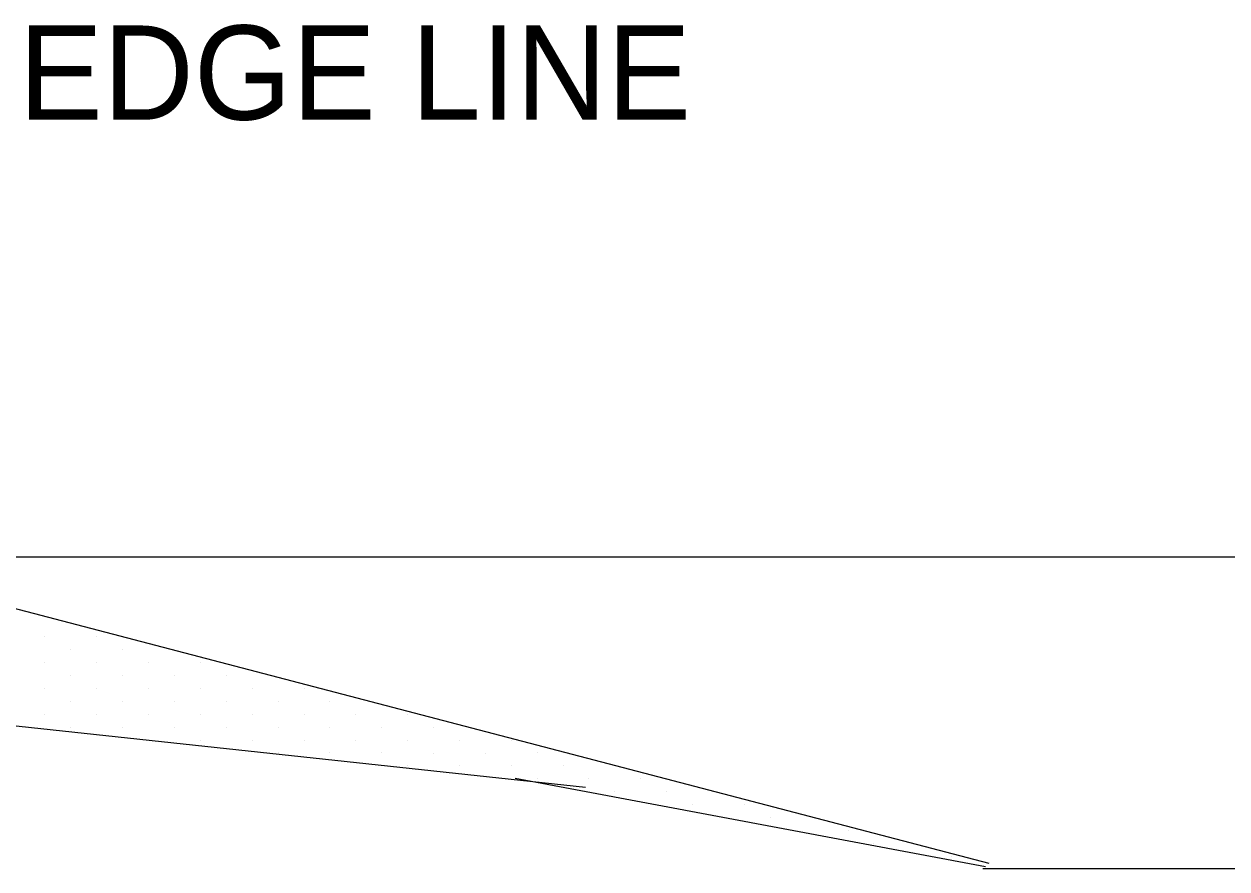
# Model space of a CAD drawing. Extents: x 12.65 to 19.62, y 5.94 to 15.74.
# Drawn here: x 13.258 to 14.024, y 13.007 to 13.545 of the extents above; entities that cross this region are included whole.
import ezdxf

# ---------------------------------------------------------------- set-up
doc = ezdxf.new("R2010")
doc.units = 0
doc.layers.add('DETL-LINE', color=7, linetype='Continuous')
doc.layers.add('DETL-NOTE', color=7, linetype='Continuous')

msp = doc.modelspace()

# ---------------------------------------------------------------- linework, layer by layer
at = {"layer": 'DETL-LINE'}
for p, q in [((13.11606, 13.20823), (13.8725, 13.01031)), ((13.0783, 13.20547), (15.17842, 13.20547)), ((13.28782, 13.16307), (13.28782, 13.16307)), ((13.2713, 13.15479), (13.2713, 13.15479)), ((13.30438, 13.15479), (13.30438, 13.15479)), ((13.28782, 13.14663), (13.28782, 13.14663)), ((13.32082, 13.14651), (13.32082, 13.14651)), ((13.2713, 13.13835), (13.2713, 13.13835)), ((13.30438, 13.13835), (13.30438, 13.13835)), ((13.3373, 13.13835), (13.3373, 13.13835)), ((13.37038, 13.13835), (13.37038, 13.13835)), ((13.28782, 13.13007), (13.28782, 13.13007)), ((13.32082, 13.13007), (13.32082, 13.13007)), ((13.35382, 13.13007), (13.35382, 13.13007)), ((13.38682, 13.13007), (13.38682, 13.13007)), ((13.2713, 13.12179), (13.2713, 13.12179)), ((13.30438, 13.12179), (13.30438, 13.12179)), ((13.3373, 13.12179), (13.3373, 13.12179)), ((13.37038, 13.12179), (13.37038, 13.12179)), ((13.4033, 13.12179), (13.4033, 13.12179)), ((13.43638, 13.12179), (13.43638, 13.12179)), ((13.6157, 13.05863), (13.12874, 13.11107)), ((13.28782, 13.11363), (13.28782, 13.11363)), ((13.32082, 13.11363), (13.32082, 13.11363)), ((13.35382, 13.11363), (13.35382, 13.11363)), ((13.38682, 13.11363), (13.38682, 13.11363)), ((13.41982, 13.11363), (13.41982, 13.11363)), ((13.45282, 13.11363), (13.45282, 13.11363)), ((13.2713, 13.10535), (13.2713, 13.10535)), ((13.30438, 13.10535), (13.30438, 13.10535)), ((13.3373, 13.10535), (13.3373, 13.10535)), ((13.37038, 13.10535), (13.37038, 13.10535)), ((13.4033, 13.10535), (13.4033, 13.10535)), ((13.43638, 13.10535), (13.43638, 13.10535)), ((13.4693, 13.10535), (13.4693, 13.10535)), ((13.50238, 13.10535), (13.50238, 13.10535)), ((13.28782, 13.09707), (13.28782, 13.09707)), ((13.32082, 13.09707), (13.32082, 13.09707)), ((13.35382, 13.09707), (13.35382, 13.09707)), ((13.38682, 13.09707), (13.38682, 13.09707)), ((13.41982, 13.09707), (13.41982, 13.09707)), ((13.45282, 13.09707), (13.45282, 13.09707)), ((13.48582, 13.09707), (13.48582, 13.09707)), ((13.51882, 13.09707), (13.51882, 13.09707)), ((13.3373, 13.08879), (13.3373, 13.08879)), ((13.37038, 13.08879), (13.37038, 13.08879)), ((13.4033, 13.08879), (13.4033, 13.08879)), ((13.43638, 13.08879), (13.43638, 13.08879)), ((13.4693, 13.08879), (13.4693, 13.08879)), ((13.50238, 13.08879), (13.50238, 13.08879)), ((13.5353, 13.08879), (13.5353, 13.08879)), ((13.5683, 13.08879), (13.5683, 13.08879)), ((13.41982, 13.08063), (13.41982, 13.08063)), ((13.45282, 13.08063), (13.45282, 13.08063)), ((13.48582, 13.08063), (13.48582, 13.08063)), ((13.51882, 13.08051), (13.51882, 13.08051)), ((13.55182, 13.08051), (13.55182, 13.08051)), ((13.58482, 13.08063), (13.58482, 13.08063)), ((13.50238, 13.07235), (13.50238, 13.07235)), ((13.5353, 13.07235), (13.5353, 13.07235)), ((13.5683, 13.07235), (13.5683, 13.07235)), ((13.6013, 13.07235), (13.6013, 13.07235)), ((13.63438, 13.07235), (13.63438, 13.07235)), ((13.87022, 13.00811), (13.57082, 13.06423)), ((13.58482, 13.06407), (13.58482, 13.06407)), ((13.61782, 13.06407), (13.61782, 13.06407)), ((13.65082, 13.06407), (13.65082, 13.06407)), ((13.63438, 13.05579), (13.63438, 13.05579)), ((13.6673, 13.05579), (13.6673, 13.05579)), ((13.68382, 13.04763), (13.68382, 13.04763)), ((13.71682, 13.04763), (13.71682, 13.04763)), ((13.7333, 13.03935), (13.7333, 13.03935)), ((13.74982, 13.03107), (13.74982, 13.03107)), ((13.78282, 13.03107), (13.78282, 13.03107)), ((13.7993, 13.02279), (13.7993, 13.02279)), ((13.84882, 13.01451), (13.84882, 13.01451)), ((15.18054, 13.00671), (13.8687, 13.00671))]:
    msp.add_line(p, q, dxfattribs=at)

# ---------------------------------------------------------------- texts
at = {"layer": 'DETL-NOTE'}
msp.add_text('EDGE LINE', height=0.06, rotation=360, dxfattribs=at).set_placement((13.25474, 13.48375))

doc.saveas('drawing.dxf')
